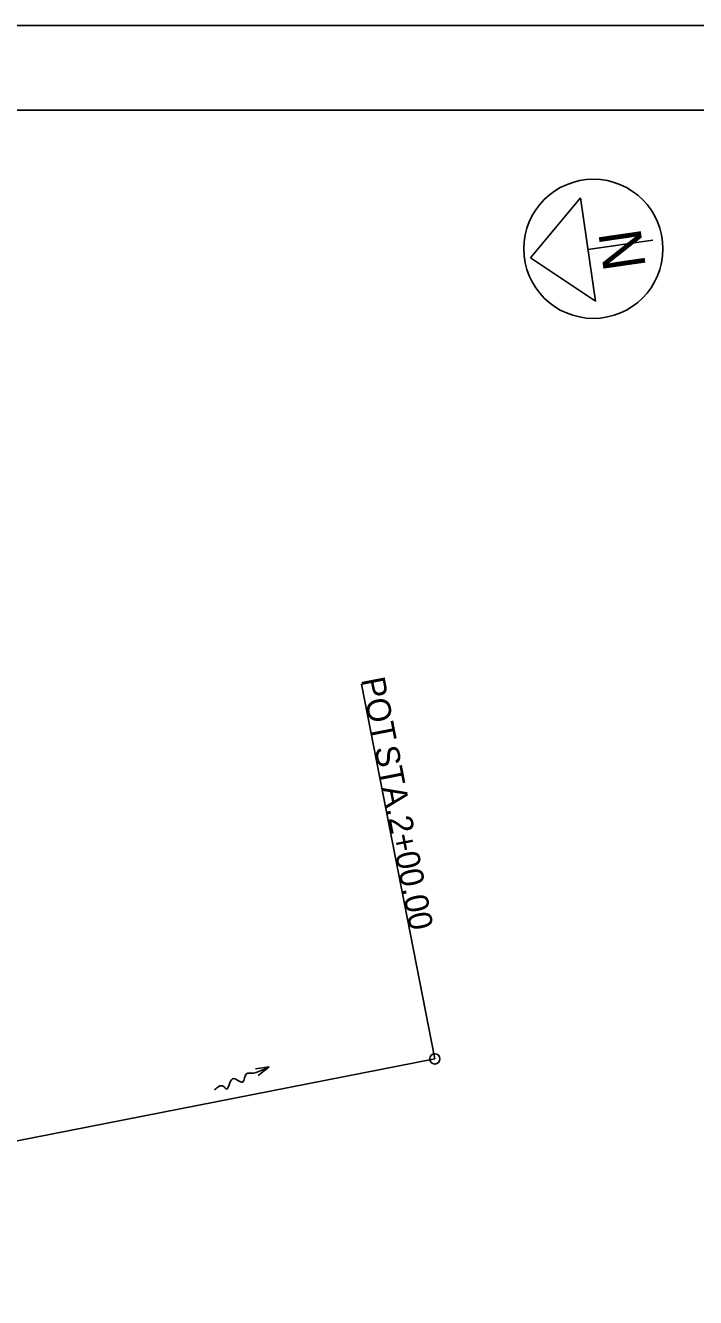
# Model space of a CAD drawing. Extents: x 0 to 2765, y 0 to 220.
# Drawn here: x 204.7 to 244.2, y 145 to 220 of the extents above; entities that cross this region are included whole.
import ezdxf

# ---------------------------------------------------------------- set-up
doc = ezdxf.new("R2010")
doc.units = 0
for name, color, linetype in [('DR_X_Culvert', 7, 'Continuous'), ('HY_P_Water_Edge', 7, 'Continuous'), ('MT_P_PCB', 7, 'Continuous'), ('MT_P_Work_Area', 7, 'Continuous'), ('PF_X_Ground_Line', 7, 'Continuous'), ('PV_P_Shoulder', 7, 'Continuous'), ('XS_X_Pavt', 7, 'Continuous')]:
    doc.layers.add(name, color=color, linetype=linetype)

msp = doc.modelspace()

# ---------------------------------------------------------------- linework, layer by layer
at = {"layer": 'DR_X_Culvert'}
msp.add_lwpolyline([(0, 0), (340, 0), (340, 220), (0, 220)], close=True, dxfattribs=at)
at = {"layer": 'HY_P_Water_Edge'}
for p, q in [((219.075, 158.632), (218.254, 158.521)), ((218.42, 158.125), (219.075, 158.632))]:
    msp.add_line(p, q, dxfattribs=at)
msp.add_spline([(219.075, 158.632), (218.308, 158.313), (217.975, 158.255), (217.755, 158.241), (217.506, 157.738), (216.9, 157.93), (216.543, 157.333), (216.352, 157.495), (215.848, 157.278)], degree=3, dxfattribs=at)
at = {"layer": 'MT_P_PCB'}
msp.add_line((228.829, 159.103), (224.509, 181.184), dxfattribs=at)
msp.add_circle((228.829, 159.103), 0.3, dxfattribs=at)
at = {"layer": 'MT_P_Work_Area'}
msp.add_line((167.983, 147.197), (228.829, 159.103), dxfattribs=at)
at = {"layer": 'PF_X_Ground_Line'}
msp.add_lwpolyline([(15, 215), (335, 215), (335, 5), (15, 5)], close=True, dxfattribs=at)
at = {"layer": 'PV_P_Shoulder'}
msp.add_circle((238.176, 206.837), 4.1, dxfattribs=at)
at = {"layer": 'XS_X_Pavt'}
for p, q in [((237.414, 209.834), (234.477, 206.302)), ((238.295, 203.746), (237.414, 209.834)), ((237.855, 206.79), (241.682, 207.344)), ((234.477, 206.302), (238.295, 203.746))]:
    msp.add_line(p, q, dxfattribs=at)
msp.add_circle((238.176, 206.837), 4.1, dxfattribs=at)

# ---------------------------------------------------------------- texts
at = {"layer": 'MT_P_PCB'}
for s, p in [('POT', (224.475, 181.465)), (' STA. ', (225.167, 177.932)), ('2+00.00', (226.074, 173.294))]:
    msp.add_text(s, height=1.4, rotation=281.07109, dxfattribs=at).set_placement(p)
at = {"layer": 'XS_X_Pavt'}
msp.add_text('N', height=2.5, rotation=98.23001, dxfattribs=at).set_placement((241.276, 205.756))

doc.saveas('drawing.dxf')
